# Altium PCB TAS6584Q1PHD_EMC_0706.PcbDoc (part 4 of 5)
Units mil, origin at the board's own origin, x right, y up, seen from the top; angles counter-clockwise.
Board outline 7086.61 x 5118.11 mil, 6 copper layers (Top Layer, GND02, SIG03, SIG04, GND05, Bottom Layer), stack 60.484 mil thick; 461 components, 247 nets, 1337 pads, 1658 vias.
Unrouted connection lines stored in the file: 67.
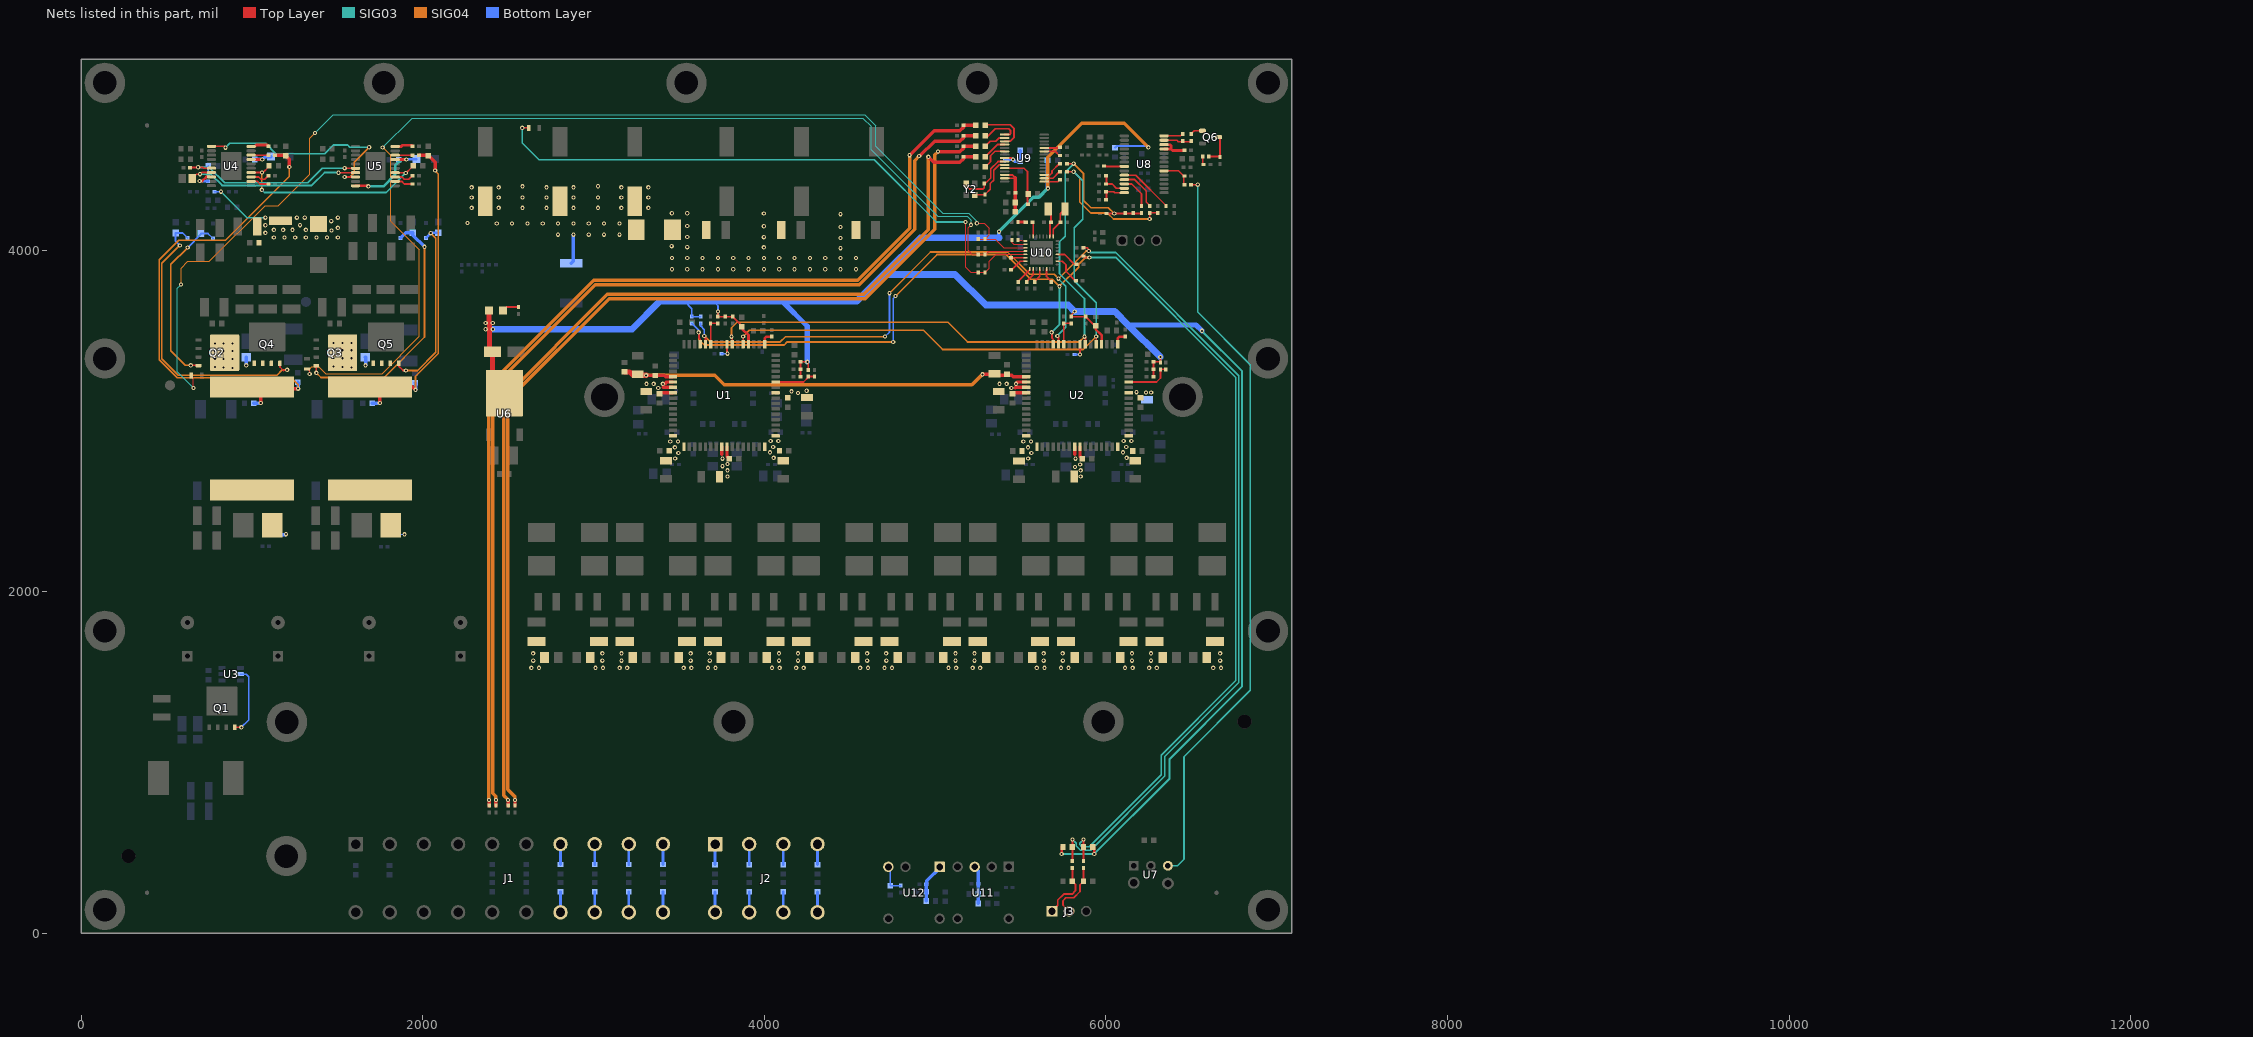
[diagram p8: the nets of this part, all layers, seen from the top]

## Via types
v1: diameter 25, hole 12, Top Layer to Bottom Layer, 1387 vias
v2: diameter 25, hole 12, Top Layer to Bottom Layer, tented both sides, 242 vias
v3: diameter 19.68, hole 7.87, Top Layer to Bottom Layer, 29 vias

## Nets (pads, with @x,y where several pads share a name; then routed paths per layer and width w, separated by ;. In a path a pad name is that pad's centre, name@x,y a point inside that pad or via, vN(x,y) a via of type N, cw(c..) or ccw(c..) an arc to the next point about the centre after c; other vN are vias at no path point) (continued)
NetC187_1: C187.1 J3.2 R123.2 | length 345.1
  Top Layer w10: J3.2@5784,130 5748.38,165.62 5748.38,191.33 5764.85,207.8 5811,207.8 5848.1,244.9 5848.1,284.66 C187.1@5868.5,305.05 R123.2@5868.5,383.6
NetC189_1: C189.1 J3.1 R122.2 | length 346.3
  Top Layer w10: J3.1@5684,130 5717.8,163.8 5717.8,195.2 5752.59,230 5801.55,230 5821,249.46 5821,288.24 C189.1@5803.5,305.75 R122.2@5803.5,383.6
NetC195_1: C195.1 R128.1 R132.2 | length 6203.1
  Top Layer w20: R128.1@2387.8,747.48 v1(2387.8,781.16) ; v1(4849.88,4557.1) 4993.71,4700.93 5144.93,4700.93 5166.04,4722.04 R132.2@5166.04,4731.47 C195.1@5237.68,4731.47
  SIG04 w20: v1(2387.8,781.16) 2385.04,783.92 2385.04,2960.18 2385.04,3020.01 2385.04,3209.6 2999.76,3824.32 3189.36,3824.32 4546.06,3824.32 4849.88,4128.14 v1(4849.88,4557.1)
NetC195_2: C195.2 U9.3 | length 295.9
  Top Layer w11: C195.2@5292.79,4731.47 5296.33,4735 5440.43,4735 5461,4714.43 5461,4660 5439.43,4638.43 U9.3@5406.61,4638.43
NetC196_1: C196.1 R129.1 R133.2 | length 6028.4
  Top Layer w20: R129.1@2498.8,747.48 v1(2498.8,781.16) ; v1(4960,4547.07) 4990.53,4516.53 5144.93,4516.53 5166.04,4537.64 R133.2@5166.04,4547.07 C196.1@5237.68,4547.07
  SIG04 w20: v1(2498.8,781.16) 2472.51,807.45 2472.51,2976.94 2472.51,3133.76 3080.57,3741.82 3237.39,3741.82 4581.18,3741.82 4960,4120.64 4960,4501.69 v1(4960,4547.07)
NetC196_2: C196.2 U9.4 | length 143.5
  Top Layer w11: C196.2@5292.79,4547.07 5334.47,4588.74 5364.47,4618.74 U9.4@5406.61,4618.74
NetC197_1: C197.1 R130.1 R134.2 | length 6137.7
  Top Layer w20: R130.1@2427.8,747.48 v1(2427.8,781.16) ; v1(4906.25,4552.44) 4910.26,4552.44 4997.28,4639.47 5144.93,4639.47 5166.04,4660.58 R134.2@5166.04,4670 C197.1@5237.68,4670
  SIG04 w20: v1(2427.8,781.16) 2427.8,803.54 2410.04,821.29 2410.04,3199.25 3010.12,3799.32 4556.41,3799.32 4879.38,4122.29 4879.38,4525.56 v1(4906.25,4552.44)
NetC197_2: C197.2 U9.1 | length 226.1
  Top Layer w11: C197.2@5292.79,4670 5310.85,4670 5352.85,4712 5431,4712 5442,4701 5442,4684 5435.8,4677.8 U9.1@5406.61,4677.8
NetC198_1: C198.1 R131.1 R135.2 | length 6009.3
  Top Layer w20: R131.1@2539.21,747.48 v1(2539.21,781.16) ; v1(5017,4578) 5144.93,4578 5166.04,4599.11 R135.2@5166.04,4608.53 C198.1@5237.68,4608.53
  SIG04 w20: v1(2539.21,781.16) 2539.21,800.59 2497.51,842.3 2497.51,3123.41 3090.92,3716.82 4591.54,3716.82 4997.87,4123.15 4997.87,4558.87 v1(5017,4578)
NetC198_2: C198.2 U9.2 | length 134.4
  Top Layer w11: C198.2@5292.79,4608.53 5322.79,4638.53 5355.53,4638.53 5375.11,4658.11 U9.2@5406.61,4658.11
NetC199_2: C199.2 U9.9 Y2.1 | length 356.3
  Top Layer w10: Y2.1@5182.95,4389.68 5182.95,4377.05 5201.57,4358.43 5278.43,4358.43 5286.78,4366.78 C199.2@5286.78,4390.28 5291.98,4390.28 5325,4423.3 5325,4477 5368.31,4520.31 U9.9@5406.61,4520.31
NetC200_2: C200.2 U9.10 Y2.3 | length 302.5
  Top Layer w10: Y2.3@5232.16,4324.72 5285.9,4324.72 C200.2@5291.78,4330.59 ; C200.2@5291.78,4326.65 5323.08,4357.95 5323.08,4391.24 5343,4411.17 5343,4469.28 5374.35,4500.63 U9.10@5406.61,4500.63
NetC201_2: C201.2 C202.1 U9.11 | length 332.6
  Top Layer w10: U9.11@5406.61,4480.94 5520.06,4480.94 5540,4461 5540,4330 C201.2@5540,4270
NetC203_1: C203.1 U9.6 | length 170.1
  Top Layer w10: C203.1@5293.55,4489.01 5323.72,4519.18 5323.72,4552.69 5350.41,4579.37 U9.6@5406.61,4579.37
NetC204_1: C204.1 C205.2 R138.1 U9.13 U9.14 | length 330.6
  Top Layer w11: U9.14@5406.61,4421.89 5466.67,4421.89 5468.89,4424.11 5451.43,4441.57 U9.13@5406.61,4441.57
  Top Layer w20: R138.1@5468.89,4226.25 C204.1@5468.89,4280 C205.2@5468.89,4337.09 5468.89,4424.11
NetC206_1: C206.1 C207.2 R142.1 U9.8 | length 215.2
  Top Layer w10: U9.8@5406.61,4540 5447,4540 v1(5455,4532)
  Bottom Layer w20: C207.2@5406.61,4520.31 5418.3,4532 v1(5455,4532) 5465.21,4521.79 C206.1@5498.58,4521.79 R142.1@5498.58,4584.29
NetC210_1: C210.1 C212.2 L18.2 U11.3 | length 221.4
  Bottom Layer w20: U11.3@5231.16,387.45 5252.73,365.88 L18.2@5252.73,175
NetC211_1: C211.1 C213.2 L19.2 U12.1 | length 232.9
  Bottom Layer w20: L19.2@4946.65,190 4947.56,190.92 C211.1@4947.56,244.19 C213.2@4947.56,287.19 4950.32,289.95 4950.32,307.1 U12.1@5031.11,387.89
NetC216_2: C216.2 U10.26 Y3.2 | length 170.9
  Top Layer w10: Y3.2@5661.42,4242.13 5677.55,4225.99 C216.2@5677.55,4165 5671.92,4159.37 U10.26@5671.92,4080.24
NetC217_2: C217.2 U10.25 Y3.1 | length 190.2
  Top Layer w10: U10.25@5691.61,4080.24 5691.61,4123.89 C217.2@5732.72,4165 5732.72,4215 Y3.1@5759.85,4242.13
NetD5_2: D5.2 R86.2 | length 99
  Top Layer w10: D5.2@2469.37,3647.93 2489.06,3667.61 R86.2@2560.18,3667.61
NetD6_2: D6.2 Q2.4 R95.2 | length 1040.1
  Top Layer w10: v1(640.71,3326.19) 684.25,3326.19 Q2.4@685.65,3324.8
  SIG04 w10: v1(622.29,4015.75) 523.89,3917.35 523.89,3411.58 609.28,3326.19 v1(640.71,3326.19)
  Bottom Layer w10: v1(622.29,4015.75) 700.1,4093.55 R95.2@700.1,4098.34 741.13,4098.34 D6.2@770.54,4068.93
NetD7_2: D7.2 Q3.4 R96.2 | length 1507.9
  Top Layer w10: v1(1376,3282.15) Q3.4@1376,3324.8
  SIG04 w10: v1(1376,3282.15) 1402.92,3255.24 1773.03,3255.24 2009.62,3491.83 v1(2009.62,4020.39)
  Bottom Layer w20: D7.2@1869.81,4073.31 1899.14,4102.64 R96.2@1940.92,4102.64 1940.92,4089.08 v1(2009.62,4020.39)
NetD8_2: D8.2 Q4.4 R97.2 | length 1733.1
  Top Layer w10: Q4.4@1162.83,3337.98 1162.83,3316.76 1183.53,3296.07 1184.7,3297.24 1202.08,3297.24 v1(1204.95,3300.11)
  SIG04 w10: v1(576.81,4028.63) 471.3,3923.12 471.3,3364.63 566.89,3269.04 1145.43,3269.04 1176.49,3300.11 v1(1204.95,3300.11)
  Bottom Layer w10: v1(576.81,4028.63) 551.87,4053.57 R97.2@551.87,4101.42 592.96,4101.42 D8.2@622.29,4072.09
NetD9_2: D9.2 Q5.4 R98.2 | length 1080.7
  Top Layer w10: Q5.4@1859.32,3337.98 1859.32,3320.73 1883.99,3296.07 v1(1900.31,3296.07)
  SIG04 w10: v1(1900.31,3296.07) 1969.36,3296.07 2075.28,3401.98 2075.28,4070.58 v1(2045.88,4099.98)
  Bottom Layer w15: D9.2@2018.5,4073.31 2047.83,4102.64 R98.2@2089.62,4102.64
NetD12_1: D12.1 Q6.3 R127.2 | length 181.5
  Top Layer w10: D12.1@6602.93,4549.69 6668,4549.69 6668,4654.09 Q6.3@6659.49,4662.6
NetD12_2: D12.2 R124.1 | length 47.2
  Top Layer w10: R124.1@6567.5,4502.45 D12.2@6567.5,4549.69
NetD13_1: D13.1 R143.2 | length 41.7
  Top Layer w16: D13.1@5484.58,4165 R143.2@5526.25,4165
NetL12_1: L12.1 R89.2 R91.1 | length 64.9
  Top Layer w20: R89.2@1105.98,2379.13 R89.2@1116.86,2390 R89.2@1125.98,2380.88
  Bottom Layer w20: R91.1@1163.06,2334.12 1194.83,2334.12 v1(1198.28,2337.57)
NetL13_1: L13.1 R90.2 R92.1 | length 35.7
  Bottom Layer w6: R92.1@1857.44,2337.36 1891.8,2337.36 v1(1892.76,2336.4)
NetQ1_4: Q1.4 U3.5 | length 407.5
  Top Layer w10: Q1.4@898.3,1206.42 v1(936.93,1206.42)
  Bottom Layer w10: U3.5@931.57,1517.81 965,1517.81 980,1502.81 980,1249.49 v1(936.93,1206.42)
NetQ6_1: Q6.1 R119.1 | length 71.5
  Top Layer w10: R119.1@6500.28,4683.62 6516.65,4700 Q6.1@6565,4700
NetR8_1: R8.1 R9.1 U1.11 | length 166
  Top Layer w10: U1.11@3686.26,3450.2 3686.26,3570.14 R9.1@3684.29,3572.11 R8.1@3727.6,3572.11
NetR10_1: R10.1 R13.2 U1.59 | length 243.6
  Top Layer w10: U1.59@4065.2,3228.74 4228.81,3228.74 4256.45,3256.39 R10.1@4256.45,3260.75 R13.2@4292.95,3260.75
NetR15_1: R15.1 U1.1 | length 79.4
  Top Layer w15: U1.1@4001.22,3450.2 4001.22,3483.79 4011.92,3494.49 R15.1@4042.64,3494.49
NetR37_1: R37.1 R38.1 U2.11 | length 166
  Top Layer w10: U2.11@5753.62,3450.2 5753.62,3570.14 5751.65,3572.11 R37.1@5794.95,3572.11
NetR39_1: R39.1 R42.2 U2.59 | length 279
  Top Layer w10: U2.59@6132.55,3228.74 6296.16,3228.74 6319.53,3252.1 R39.1@6319.53,3302.99 R42.2@6351.02,3302.99
NetR44_1: R44.1 U2.1 | length 79.4
  Top Layer w15: U2.1@6068.58,3450.2 6068.58,3483.79 6079.28,3494.49 R44.1@6109.99,3494.49
NetR67_2: R67.2 U4.13 | length 115
  Top Layer w10: U4.13@994.17,4429.4 1039,4429.4 1051.99,4416.41 1060.19,4416.41 1074.15,4416.41 R67.2@1095.12,4437.38
NetR73_2: R73.2 U4.12 | length 108.2
  Top Layer w10: U4.12@994.17,4403.81 1030.56,4403.81 1046.15,4388.22 1069.43,4388.22 R73.2@1095.86,4388.22
NetR74_2: R74.2 U4.8 | length 129.1
  Top Layer w15: v1(692.82,4405.5) 707.69,4405.5 731.59,4429.4 U4.8@761.89,4429.4
  Bottom Layer w15: v1(692.82,4405.5) 694.51,4403.81 R74.2@742.2,4403.81
NetR76_2: R76.2 U4.20 | length 109.5
  Top Layer w16: U4.20@994.17,4608.54 1015.86,4608.54 1023.84,4616.52 1089.05,4616.52 R76.2@1097.03,4608.54
NetR77_2: R77.2 U4.18 | length 101.7
  Top Layer w10: U4.18@994.17,4557.36 994.37,4557.16 R77.2@1095.78,4557.16
NetR80_2: R80.2 U5.13 | length 115.1
  Top Layer w10: U5.13@1837.8,4429.01 1879.18,4429.01 1891.78,4416.41 1918.05,4416.41 R80.2@1939.02,4437.38
NetR82_2: R82.2 U5.12 | length 108.3
  Top Layer w10: U5.12@1837.8,4403.42 1876.2,4403.42 1891.4,4388.22 R82.2@1939.84,4388.22
NetR83_2: R83.2 U5.20 | length 108.5
  Top Layer w16: U5.20@1837.8,4608.15 1874.73,4608.15 1881.52,4614.93 1933.87,4614.93 R83.2@1940.65,4608.15
NetR84_2: R84.2 U5.18 | length 97.1
  Top Layer w10: U5.18@1837.8,4556.96 1934.64,4556.96 R84.2@1934.82,4556.79
NetR106_1: R106.1 U7.3 | length 4383.7
  Top Layer w10: R106.1@6502.24,4384.02 v1(6537.59,4384.02)
  SIG03 w10: U7.3@6362.9,395.86 6418.9,395.86 6456.85,433.81 6456.85,1034.72 6845.47,1423.34 6845.47,3330.53 6537.59,3638.41 v1(6537.59,4384.02)
NetR108_1: R108.1 R112.2 U8.13 | length 162.6
  Top Layer w10: R108.1@6003.62,4436.19 6003.62,4388.19 6035.81,4388.19 6061.17,4362.83 U8.13@6107.72,4362.83
NetR109_1: R109.1 R113.2 U8.14 | length 154.5
  Top Layer w10: R109.1@6003.62,4295 6003.62,4343 6045,4343 6050.76,4337.24 U8.14@6107.72,4337.24
NetR110_2: R110.2 U8.8 | length 120.4
  Top Layer w10: R110.2@5988.69,4494 6000.5,4494 6003.71,4490.79 U8.8@6107.72,4490.79
NetR111_1: R111.1 U8.25 U8.26 | length 182
  Top Layer w16: U8.25@6340,4593.15 6382,4593.15 ; U8.26@6340,4618.74 6375.29,4618.74 6382,4612.03 6382,4593.15 ; R111.1@6455,4585 6390.15,4585 6382,4593.15
NetR114_1: R114.1 U8.28 | length 115.7
  Top Layer w10: U8.28@6340,4669.92 6436.3,4669.92 R114.1@6450,4683.62
NetR114_2: R114.2 R119.2 U8.27 | length 163.6
  Top Layer w10: U8.27@6340,4644.33 6415.67,4644.33 6423.62,4636.38 6450,4636.38 R119.2@6500.28,4636.38
NetR115_1: R115.1 U8.11 | length 249
  Top Layer w10: U8.11@6107.72,4414.02 6168.98,4414.02 6236,4347 6236,4282.63 R115.1@6256.23,4262.4
NetR116_1: R116.1 U8.10 | length 317.6
  Top Layer w10: U8.10@6107.72,4439.61 6174.74,4439.61 R116.1@6351.94,4262.4
NetR117_1: R117.1 U8.12 | length 192.6
  Top Layer w10: U8.12@6107.72,4388.43 6150.22,4388.43 6208.37,4330.28 R117.1@6208.37,4262.4
NetR136_2: R136.2 U9.25 | length 98.5
  Top Layer w10: U9.25@5638.9,4579.37 5703.27,4579.37 R136.2@5727.4,4555.24
NetR137_2: R137.2 U9.26 | length 90.1
  Top Layer w10: U9.26@5638.9,4599.06 5723.5,4599.06 R137.2@5727.4,4602.95
NetR139_2: R139.2 U9.18 | length 122.6
  Top Layer w10: U9.18@5638.9,4441.57 5673.02,4441.57 5684,4452.56 5684,4464.13 R139.2@5727.4,4507.53
NetR140_2: R140.2 U9.16 | length 92.6
  Top Layer w10: U9.16@5638.9,4402.2 5717.5,4402.2 R140.2@5727.4,4412.1
NetR141_2: R141.2 U9.17 | length 104.2
  Top Layer w10: U9.17@5638.9,4421.89 5689.48,4421.89 R141.2@5727.4,4459.81
NetR143_1: R143.1 U10.31 | length 84.8
  Top Layer w10: U10.31@5573.5,4080.24 R143.1@5573.5,4165
NetR146_1: R146.1 U10.7 | length 100.6
  Top Layer w10: R146.1@5448.3,3886.54 5498.3,3936.54 U10.7@5528.22,3936.54
NetR147_1: R147.1 U10.6 | length 79.9
  Top Layer w10: R147.1@5448.3,3956.22 U10.6@5528.22,3956.22
NetR148_1: R148.1 U10.12 | length 84.7
  Top Layer w10: R148.1@5583.77,3818.62 5612.87,3847.72 U10.12@5612.87,3891.26
NetR149_1: R149.1 U10.14 | length 84.4
  Top Layer w10: U10.14@5652.24,3891.26 5652.24,3846.92 R149.1@5680.54,3818.62
NetR150_1: R150.1 U10.18 | length 172.3
  Top Layer w10: U10.18@5717.2,3936.54 5744.46,3936.54 5766,3915 5766,3876.41 R150.1@5819.76,3822.65
NetR151_1: R151.1 U10.20 | length 126.4
  Top Layer w10: U10.20@5717.2,3975.91 5757.09,3975.91 5814.56,3918.44 R151.1@5819.76,3918.44
NetR152_1: R152.1 U10.1 | length 45.9
  Top Layer w6: R152.1@5484.53,4059.94 5506,4059.94 5511.3,4054.65 U10.1@5528.22,4054.65
NetR153_1: R153.1 U10.2 | length 96.9
  Top Layer w6: R153.1@5449.53,4059.94 5449.53,4046.47 5461.04,4034.96 U10.2@5528.22,4034.96
NetR154_1: R154.1 R156.2 U12.4 | length 171.8
  Bottom Layer w10: U12.4@4731.11,387.89 4736.22,382.78 R156.2@4736.22,279.65 R154.1@4797.63,279.65
NetR158_2: R158.2 U10.9 | length 100.3
  Top Layer w10: R158.2@5487,3818.62 5553.81,3885.43 U10.9@5553.81,3891.26
NetR159_2: R159.2 U10.10 | length 88.4
  Top Layer w10: R159.2@5535.38,3818.62 5573.5,3856.74 U10.10@5573.5,3891.26
NTC1: C228.2 R52.1 RT1.2 U10.3 | length 6778.9
  Top Layer w6: RT1.2@643.84,3267.34 656.25,3254.93 v1(656.25,3194.2) ; v1(5243.97,4158.32) 5288.61,4158.32 5316.44,4130.5 5316.44,4090.52 C228.2@5291.98,4066.06 ; R52.1@5252.91,4066.06 C228.2@5291.98,4066.06 ; U10.3@5528.22,4015.28 5401.11,4015.28 5350.32,4066.06 C228.2@5291.98,4066.06
  SIG04 w6: v1(583.79,3799.38) 583.79,3895.89 622.29,3934.39 748.96,3934.39 1075.72,4261.16 1152.82,4261.16 1337.01,4445.35 1337.01,4655.81 v1(1368.33,4687.14)
  SIG03 w6: v1(583.79,3799.38) 560.68,3776.27 560.68,3289.77 v1(656.25,3194.2) ; v1(1368.33,4687.14) 1475.19,4794 4586.22,4794 4652.22,4728 4652.22,4608.8 5043.22,4217.8 5195.21,4217.8 5243.97,4169.04 v1(5243.97,4158.32)
NTC2: C229.2 R65.1 RT2.2 U10.4 | length 6395.3
  Top Layer w6: RT2.2@1322.47,3305.01 1337.26,3290.22 v1(1337.26,3274.97) ; v1(5209.88,4148.8) 5193.25,4132.16 5193.25,3999.73 5217.97,3975.02 R65.1@5252.91,3975.02 C229.2@5291.98,3975.02 5312.55,3995.59 U10.4@5528.22,3995.59
  SIG04 w6: v1(1337.26,3274.97) 1337.26,3303.99 1350.02,3316.76 1390.93,3316.76 1430.03,3277.66 1760.66,3277.66 1980,3497 1980,4002.01 1810.88,4171.12 1810.88,4556.06 v1(1764.77,4602.17)
  SIG03 w6: v1(1764.77,4602.17) 1936.61,4774 4577,4774 4626,4725 4626,4588.2 5015.74,4198.46 5187,4198.46 5209.88,4175.58 v1(5209.88,4148.8)
NTC3: C230.2 R66.1 RT3.2 U10.5 | length 3603.1
  Top Layer w6: v1@5177.96,4159.37 5177.96,3900.43 5207.07,3871.31 R66.1@5252.91,3871.31 C230.2@5291.98,3871.31 5316.44,3895.77 5316.44,3935.36 5356.98,3975.91 5388.88,3975.91 5389.04,3976.06 5420.95,3976.06 5421.1,3975.91 5428.25,3975.91 5428.41,3976.06 5460.32,3976.06 5460.47,3975.91 U10.5@5528.22,3975.91
  Top Layer w10: v1(2581.85,4717) RT3.2@2620.55,4717
  SIG03 w10: v1(2581.85,4717) 2581.85,4628.14 2679.99,4530 4643.59,4530 5007.59,4166 v1(5177.96,4166)
PVDD: C2.1 C3.1 C4.1 C5.1 C6.1 C7.1 C8.1 C9.1 C15.1 C17.1 C60.1 C61.1 C62.1 C63.1 C64.1 C65.1 C66.1 C67.1 C73.1 C75.1 J5.2 R103.2 R104.2 R105.2 U1.22 U1.23 U1.24 U1.32 U1.33 U1.40 U1.41 U1.48 U1.49 U1.57 U2.22 U2.23 U2.24 U2.32 U2.33 U2.40 U2.41 U2.48 U2.49 U2.57 | length 634.8
  Top Layer w20: C6.1@3385.71,3160.67 3390.78,3165.75 U1.24@3464.8,3165.75 ; 3407.97,3197.24 U1.23@3464.8,3197.24 ; 3420,3220 3428.74,3228.74 U1.22@3464.8,3228.74 ; 3749.25,2805.42 U1.40@3749.25,2849.8 ; U1.41@3780.75,2849.8 3780.75,2792.95 C7.1@3793.7,2780 ; C65.1@5453.06,3160.67 5458.14,3165.75 U2.24@5532.16,3165.75 ; 5469.07,3194.69 5471.63,3197.24 U2.23@5532.16,3197.24 ; v2(5472.61,3218.28) 5483.08,3228.74 U2.22@5532.16,3228.74 ; 5816.61,2805.42 U2.40@5816.61,2849.8 ; U2.41@5848.1,2849.8 5848.1,2792.95 C64.1@5861.05,2780
  other v1: 4054.22,2784.86 6121.57,2784.86 4032.06,2816.79 6099.42,2816.79 4051.32,2848.77 6118.68,2848.77 4036.34,2882.65 6103.69,2882.65 4081.3,2883.3 6148.65,2883.3 4197.06,3164.08 6234.4,3166.73 6264.42,3166.73 6179.09,3169.3 4157.88,3173.83 4247.18,3177.61 3458.32,3889.08 3548.1,3889.08 3637.87,3889.08 3727.65,3889.08 3817.43,3889.08 3907.2,3889.08 3996.98,3889.08 4086.75,3889.08 4176.53,3889.08 4266.31,3889.08 4356.08,3889.08 4445.86,3889.08 4535.64,3889.08 3458.32,3955 3548.1,3955 3637.87,3955 3727.65,3955 3817.43,3955 3907.2,3955 3996.98,3955 4086.75,3955 4176.53,3955 4266.31,3955 4356.08,3955 4445.86,3955 4535.64,3955 4445.8,4012.64 3996.2,4017.11 3548.1,4018.2 3457.08,4024.02 4445.8,4072.25 3996.2,4076.73 3548.1,4077.82 4445.8,4136.43 3996.2,4140.91 3548.1,4142 4445.8,4211.43 3996.2,4215.91 3458,4217 3548.1,4217
  other v2: 3784.43,2674.8 5851.78,2674.8 3784.43,2711.52 5851.78,2711.52 5818.18,2730.55 3754.82,2735.55 5848.78,2745.24 3784.43,2748.24 3754.82,2779.48 5822.18,2779.48 3477.25,2780.79 5544.61,2780.79 3495.83,2812.92 5563.18,2812.92 3475.49,2846.24 5542.84,2846.24 3448.63,2879.95 5515.98,2879.95 3493.32,2880.26 5560.67,2880.26 3378.29,3194.1 5445.65,3194.1 3309.63,3218 3351.11,3218 5376.99,3218 5418.46,3218 3405.26,3218.28
RES: C141.1 C219.1 U4.14 U5.14 | length 1232.8
  Top Layer w10: U4.14@994.17,4454.99 1054.19,4454.99 1056.37,4457.18 1065.92,4457.18 C141.1@1096.22,4487.48 ; U5.14@1837.8,4454.6 1896.23,4454.6 1899.75,4451.08 1936.14,4487.48 C219.1@1939.84,4487.48
  SIG04 w10: v1(1056.61,4353.99) 1056.61,4454.36 v1(1057.3,4455.05)
  SIG03 w10: v1(1056.61,4353.99) 1072.6,4338 1784.67,4338 v1(1899.75,4453.08)
RXIN: C178.1 R106.2 U8.20 | length 178.6
  Top Layer w10: U8.20@6340,4465.2 6425,4465.2 6455,4435.2 R106.2@6455,4384.02
SCL: R1.1 R120.1 R123.1 R144.2 U1.13 U2.13 | length 7890.3
  Top Layer w10: v1(3614.73,3519.37) 3616.89,3517.2 3616.89,3485.82 3623.27,3479.44 U1.13@3623.27,3450.2 ; v1(5682.08,3519.37) 5684.25,3517.2 5684.25,3485.82 5690.62,3479.44 U2.13@5690.62,3450.2 ; R144.2@5868.07,3966.33 5876.01,3958.38 v1(5902.81,3958.38) ; R123.1@5868.5,422.97 v1(5868.5,550)
  SIG04 w10: v1(3614.73,3519.37) 3614.73,3477.86 3647.59,3445 4116.11,3445 4134.68,3463.57 4753.43,3463.57 v1(4754,3463) ; v1(4768,3732) 5010.86,3974.86 5415.97,3974.86 5559.78,3831.05 5685.35,3831.05 v1(5727.4,3789) 5840,3901.6 5840,3917.25 5881.14,3958.38 v1(5902.81,3958.38)
  SIG03 w10: v1(5682.08,3519.37) 5727.4,3564.68 v1(5727.4,3789) ; v1(5868.5,550) 5846,527.5 5846,520 5859,507 5901.61,507 6324,929.39 6324,1043.77 6760.78,1480.55 6760.78,3254.94 6057.33,3958.38 v1(5902.81,3958.38)
  Bottom Layer w10: R1.1@3575.2,3572.11 3614.73,3532.57 v1(3614.73,3519.37) ; v1(4754,3463) 4754,3718 v1(4768,3732)
SCLK: C185.1 R115.2 R141.1 U1.5 U2.5 | length 4073.4
  Top Layer w10: U1.5@3875.24,3450.2 v1(3875.24,3495.21) ; R141.1@5774.64,4459.81 v1(5811,4459.81) ; U2.5@5942.59,3450.2 v1(5942.59,3495.21) ; v1(6256.23,4182.94) R115.2@6256.22,4219.09 C185.1@6304.08,4219.09
  SIG04 w10: v1(3875.24,3495.21) 3911.03,3531 4931.25,3531 5043.22,3419.03 5866.42,3419.03 v1(5942.59,3495.21) ; v1(5811,4459.81) 5847,4423.81 5847,4283 5912.2,4217.8 6008.98,4217.8 6043.84,4182.94 v1(6256.23,4182.94)
  SIG03 w10: v1(5811,4459.81) 5864,4406.81 5864,4181 5814,4131 5814,3821 5942.59,3692.41 v1(5942.59,3495.21)
SDA: R3.1 R121.1 R122.1 R145.2 U1.12 U2.12 | length 7940.5
  Top Layer w10: v1(3647.59,3498.56) 3654.76,3491.39 U1.12@3654.76,3450.2 ; v1(5714.95,3498.56) 5722.12,3491.39 U2.12@5722.12,3450.2 ; R122.1@5803.5,422.97 v1(5803.5,550) ; R145.2@5868.07,4014.22 5889.5,4014.22 5899.27,4004.45 v1(5899.27,3995.3)
  SIG04 w10: v1(3647.59,3498.56) 3682.58,3463.57 4092.94,3463.57 4123.56,3494.19 4705.2,3494.19 v1(4706.21,3495.21) ; v1(4732,3749) 4972.86,3989.86 5423.7,3989.86 5554.64,3858.91 5697.21,3858.91 v1(5722.12,3834) 5814,3925.88 5883.42,3995.3 v1(5899.27,3995.3)
  SIG03 w10: v1(5714.95,3498.56) 5764.84,3548.45 5764.84,3789 5722.12,3831.72 v1(5722.12,3834) ; v1(5803.5,550) 5826,527.5 5826,511.72 5850.72,487 5909.9,487 6344,921.1 6344,1035.49 6777.92,1469.41 6777.92,3266.08 6057,3987 5907.57,3987 v1(5899.27,3995.3)
  Bottom Layer w10: R3.1@3626.19,3572.11 3626.19,3557.11 3647.59,3535.71 v1(3647.59,3498.56) ; v1(4706.21,3495.21) 4732,3521 v1(4732,3749)
SDIN: C188.1 R117.2 R125.2 R126.2 R139.1 U1.7 U2.7 | length 4085
  Top Layer w10: v1(3807.06,3494.19) 3812.24,3489.01 U1.7@3812.24,3450.2 ; R139.1@5774.64,4507.53 v1(5811,4507.53) ; v1(5874.42,3494.19) 5879.6,3489.01 U2.7@5879.6,3450.2 ; R125.2@6003.62,4215.16 R117.2@6208.37,4215.16
  SIG04 w10: v1(3807.06,3494.19) 3807.06,3546 3839.49,3578.42 5074.58,3578.42 5189.43,3463.57 5843.8,3463.57 v1(5874.42,3494.19) ; v1(5811,4507.53) 5868,4450.53 5868,4294 5912.5,4249.5 6014.3,4249.5 v1(6048.64,4215.16)
  SIG03 w10: v1(5811,4507.53) 5761,4457.53 5761,4083 5728,4050 5728,3863.66 5874.42,3717.24 v1(5874.42,3494.19)
SDOUT1: R40.1 U2.8 | length 96.6
  Top Layer w10: v1(5848.1,3390.15) U2.8@5848.1,3450.2
  Bottom Layer w10: R40.1@5814.57,3387.99 R40.1@5816.74,3390.15 ; R40.1@5814.57,3390.15 R40.1@5816.74,3390.15 ; v1(5848.1,3390.15) R40.1@5816.74,3390.15
SDOUT2: R11.1 U1.8 | length 92.1
  Top Layer w10: U1.8@3780.75,3450.2 3780.75,3397.15 v1(3783.1,3394.8)
  Bottom Layer w10: R11.1@3747.33,3394.8 v1(3783.1,3394.8)
SPK_OUT1+: C49.1 C57.1 J1.14 R30.2 | length 120
  Bottom Layer w16: J1.14@2806,123 C57.1@2806,243
  other v1: 3010.34,1554.79 3055.25,1554.75 3051.04,1597.09 3051.04,1639.98
SPK_OUT1-: C50.1 C58.1 J1.13 R31.2 | length 120
  Bottom Layer w16: C58.1@2806,403 J1.13@2806,523
  other v1: 2635.24,1554.79 2679.27,1554.79 2646.23,1597.09 2645.52,1639.98
SPK_OUT2+: C47.1 C55.1 J1.16 R28.2 | length 120
  Bottom Layer w16: J1.16@3006,123 C55.1@3006,243
  other v1: 3527.2,1554.79 3572.11,1554.75 3567.9,1597.09 3567.9,1639.98
SPK_OUT2-: C48.1 C56.1 J1.15 R29.2 | length 120
  Bottom Layer w16: C56.1@3006,403 J1.15@3006,523
  other v1: 3152.1,1554.79 3196.13,1554.79 3163.09,1597.09 3162.38,1639.98
SPK_OUT3+: C45.1 C53.1 J1.18 R26.2 | length 120
  Bottom Layer w16: J1.18@3206,123 C53.1@3206,243
  other v1: 4044.06,1554.79 4088.97,1554.75 4084.76,1597.09 4084.76,1639.98
SPK_OUT3-: C46.1 C54.1 J1.17 R27.2 | length 120
  Bottom Layer w16: C54.1@3206,403 J1.17@3206,523
  other v1: 3668.96,1554.79 3712.99,1554.79 3679.95,1597.09 3679.24,1639.98
SPK_OUT4+: C43.1 C51.1 J1.20 R24.2 | length 120
  Bottom Layer w16: J1.20@3406,123 C51.1@3406,243
  other v1: 4560.92,1554.79 4605.83,1554.75 4601.62,1597.09 4601.62,1639.98
SPK_OUT4-: C44.1 C52.1 J1.19 R25.2 | length 120
  Bottom Layer w16: C52.1@3406,403 J1.19@3406,523
  other v1: 4185.83,1554.79 4229.85,1554.79 4196.81,1597.09 4196.1,1639.98
SPK_OUT5+: C107.1 C115.1 J2.2 R59.2 | length 120
  Bottom Layer w16: J2.2@3711,122.65 C115.1@3711,242.65
  other v1: 5077.78,1554.79 5122.69,1554.75 5118.48,1597.09 5118.48,1639.98
SPK_OUT5-: C108.1 C116.1 J2.1 R60.2 | length 120
  Bottom Layer w16: C116.1@3711,402.65 J2.1@3711,522.65
  other v1: 4702.69,1554.79 4746.71,1554.79 4713.68,1597.09 4712.96,1639.98
SPK_OUT6+: C105.1 C113.1 J2.4 R57.2 | length 120
  Bottom Layer w16: J2.4@3911,122.65 C113.1@3911,242.65
  other v1: 5594.64,1554.79 5639.55,1554.75 5635.34,1597.09 5635.34,1639.98
SPK_OUT6-: C106.1 C114.1 J2.3 R58.2 | length 120
  Bottom Layer w16: C114.1@3911,402.65 J2.3@3911,522.65
  other v1: 5219.55,1554.79 5263.57,1554.79 5230.54,1597.09 5229.82,1639.98
SPK_OUT7+: C103.1 C111.1 J2.6 R55.2 | length 120
  Bottom Layer w16: J2.6@4111,122.65 C111.1@4111,242.65
  other v1: 6111.5,1554.79 6156.41,1554.75 6152.2,1597.09 6152.2,1639.98
SPK_OUT7-: C104.1 C112.1 J2.5 R56.2 | length 120
  Bottom Layer w16: C112.1@4111,402.65 J2.5@4111,522.65
  other v1: 5736.41,1554.79 5780.43,1554.79 5747.4,1597.09 5746.68,1639.98
SPK_OUT8+: C101.1 C109.1 J2.8 R53.2 | length 120
  Bottom Layer w16: J2.8@4311,122.65 C109.1@4311,242.65
  other v1: 6628.36,1554.79 6673.27,1554.75 6669.06,1597.09 6669.06,1639.98
SPK_OUT8-: C102.1 C110.1 J2.7 R54.2 | length 120
  Bottom Layer w16: C110.1@4311,402.65 J2.7@4311,522.65
  other v1: 6253.27,1554.79 6297.29,1554.79 6264.26,1597.09 6263.54,1639.98
SS: C128.1 U4.7 U5.7 | length 1112.9
  Top Layer w10: C128.1@663.71,4420.32 C128.1@648.75,4420.32 674.12,4445.69 v1(695.08,4445.69) ; v1@695.08,4445.27 704.81,4454.99 U4.7@761.89,4454.99 ; v1(1505.65,4453.99) 1506.27,4454.6 U5.7@1605.51,4454.6 U5.7@1604.9,4453.99
  SIG03 w10: v1(695.08,4445.69) 758.47,4445.69 824.14,4380.02 1348.98,4380.02 1424.01,4455.05 1504.59,4455.05 v1(1505.65,4453.99)
SW1: C132.2 C154.1 C156.1 D11.2 L12.2 Q2.5 Q2.6 Q2.7 Q2.8 Q2.9@839.19,3399.8 Q4.1 Q4.2 Q4.3 R77.1 | length 3145.5
  Top Layer w20: L12.2@998.21,3199.74 L12.2@1008.49,3189.46 ; v1(1050.58,3105.15) 1050.58,3147.37 L12.2@1008.49,3189.46 ; R77.1@1135.15,4557.16 1193.64,4557.16 1218.03,4532.77 v1(1218.03,4487.48) ; v1(1269.76,3189.46) L12.2@1008.49,3189.46
  SIG04 w10: v1(1218.03,4487.48) 1218.03,4432.36 844.36,4058.69 570.43,4058.69 456.3,3944.56 456.3,3358.42 560.68,3254.04 1228.96,3254.04 1269.76,3213.24 v1(1269.76,3189.46)
  Bottom Layer w20: D11.2@965.06,3374.53 965.48,3374.12 v1(965.48,3326.19) ; C154.1@1010.29,3104.94 1010.5,3105.15 v1(1050.58,3105.15) ; C156.1@1267.77,3227.04 1269.76,3225.04 v1(1269.76,3189.46)
  other v1: 885.34,3311.59 832.92,3314.4 781.57,3316.76 781.57,3365.01 832.92,3364.63 885.34,3364.63 781.57,3411.58 832.92,3411.58 885.34,3411.58 781.57,3455 832.92,3455 885.34,3455
SW2: C144.2 C155.1 C157.1 D10.2 L13.2 Q3.5 Q3.6 Q3.7 Q3.8 Q3.9@1529.55,3399.8 Q5.1 Q5.2 Q5.3 R84.1 | length 2031.3
  Top Layer w20: v1(1747.98,3105.39) 1747.98,3142.67 L13.2@1690.91,3199.74 1936.82,3199.74 v1@1953.98,3182.58 ; R84.1@1978.39,4556.77 2028.84,4556.77 C144.2@2032.19,4553.42 2034.7,4553.42 2071.85,4516.27 v1(2071.85,4467.4)
  SIG04 w10: v1(1956.98,3182.58) 1956.98,3262.47 2090.28,3395.77 2090.28,4446.93 2071.85,4465.35 v1(2071.85,4467.4)
  Bottom Layer w20: D10.2@1663.36,3374.53 1664.32,3373.57 v1(1664.32,3326.38) ; C155.1@1703.24,3104.94 1703.69,3105.39 v1(1747.98,3105.39) ; C157.1@1953.98,3224.24 1956.98,3221.24 v1(1956.98,3182.58)
  other v1: 1580.79,3314.67 1528.37,3317.47 1477.02,3319.83 1477.02,3368.09 1528.37,3367.71 1580.79,3367.71 1477.02,3414.66 1528.37,3414.66 1580.79,3414.66 1477.02,3458.07 1528.37,3458.07 1580.79,3458.07
SYNC: U4.1 U5.8 | length 1303.2
  Top Layer w10: U4.1@761.89,4608.54 836.15,4608.54 v1(843.97,4600.72) ; v1(1541.97,4429.01) U5.8@1605.51,4429.01
  SIG04 w10: v1(1541.97,4429.01) 1572.61,4429.01 1598.2,4454.6 1598.2,4516.36 v1(1685.18,4603.34)
  SIG03 w10: v1(843.97,4600.72) 869.23,4625.98 1079.58,4625.98 1139.37,4566.19 1424.61,4566.19 1474.94,4616.52 1559.26,4616.52 1572.44,4603.34 v1(1685.18,4603.34)
UVLO: C123.1 R69.1 R70.2 U4.6 U5.6 | length 1231.4
  Top Layer w10: R69.1@637.22,4484 638.48,4485.26 711.34,4485.26 716.02,4480.59 U4.6@761.89,4480.59 ; v1(1541.97,4480.59) 1542.36,4480.19 U5.6@1605.51,4480.19
  SIG03 w10: v1(684.16,4486.26) 685.18,4485.24 749.39,4485.24 839.61,4395.02 1325.38,4395.02 1410.95,4480.59 v1(1541.97,4480.59)
  Bottom Layer w10: v1(684.16,4486.26) 736.38,4486.26 C123.1@743.3,4493.19 R70.2@743.3,4445.69
V_boost: C167.1 C168.1 C169.2 C170.2 C171.2 J5.1 L14.2 R61.1 R101.2 R102.1 | length 533.9
  SIG03 w10: v1(817.82,4343.34) 970.34,4190.83 v1(1077.2,4190.83)
  Bottom Layer w10: R61.1@779.36,4343 817.48,4343 v1(817.82,4343.34)
  Bottom Layer w20: R102.1@2869,3924 2881.36,3936.36 v1(2881.36,4091.63)
  other v1: 1127.43,4075 1189.75,4075 1252.08,4075 1314.4,4075 1376.73,4075 1439.06,4075 1501.61,4075 2791.58,4091.63 2971.13,4091.63 3060.91,4091.63 3150.69,4091.63 1077.2,4102.21 1465,4115.25 1127.43,4119.84 1182.09,4119.84 1236.75,4119.84 1314.4,4119.84 1501.61,4131.42 1077.2,4146.52 1280.15,4147.4 2432.47,4157.43 2522.25,4157.43 2612.03,4157.43 2701.8,4157.43 2791.58,4157.43 2881.36,4157.43 2971.13,4157.43 3060.91,4157.43 3150.69,4157.43 2261.24,4160.34 1463.25,4170.4 1261.49,4190.83 1308.31,4190.83 1501.61,4190.83 2285.56,4248.94 2443.56,4248.94 2582.94,4248.94 2723.91,4248.94 2881.91,4248.94 3024.95,4248.94 3162.2,4248.94 3320.2,4248.94 2285.56,4308.94 2443.56,4308.94 2582.94,4308.94 2723.91,4308.94 2881.91,4308.94 3024.95,4308.94 3162.2,4308.94 3320.2,4308.94 2285.56,4368.94 2443.56,4368.94 2723.91,4368.94 2881.91,4368.94 3162.2,4368.94 3320.2,4368.94 2582.94,4374.32 3024.95,4375
VBAT: C16.1 C18.1 C74.1 C76.1 L1.1 U1.21 U2.21 | length 2578.6
  Top Layer w20: v2(3307.72,3268.11) 3308.83,3267 C16.1@3360,3267 3361.11,3268.11 3413.88,3268.11 3421.76,3260.24 U1.21@3464.8,3260.24 ; v1(5277.05,3273.95) 5343.35,3273.95 C76.1@5346.95,3277.55 5355.57,3268.94 5448.3,3268.94 5457,3260.24 U2.21@5532.16,3260.24
  Top Layer w30: L1.1@3180.41,3287.97 3181.2,3287.18 3210.97,3287.18 3230.04,3268.11 v2(3307.72,3268.11)
  SIG04 w20: v2(3307.72,3268.11) 3708.97,3268.11 3764.78,3212.3 5215.39,3212.3 v1(5277.05,3273.95)
VCC: C1.1 C59.1 C143.1 D5.1 L15.2 L16.2 L17.2 R1.2 R2.2 R3.2 R4.2 R5.2 R6.2 R7.2 R8.2 R10.2 R32.2 R33.2 R35.2 R36.2 R37.2 R39.2 R120.2 R121.2 U1.4 U2.4 U6.4 | length 13099.4
  Top Layer w8: R2.2@3814.21,3611.48 3867.8,3557.89 C1.1@3867.8,3552.45
  Top Layer w10: v1(3728.42,3642.03) 3728.42,3612.3 R8.2@3727.6,3611.48 R5.2@3770.9,3611.48 R2.2@3814.21,3611.48 ; R4.2@4210.68,3259.09 R6.2@4210.68,3303.09 R7.2@4210.68,3347.08 4211.04,3346.73 v1(4251,3346.73) 4256.45,3341.28 R10.2@4256.45,3300.12 ; v1(5816.69,3641.51) 5795.93,3620.75 R37.2@5795.93,3611.48 R32.2@5881.57,3611.48 5940.15,3552.89 C59.1@5940.15,3552.45 ; R33.2@6277.83,3259.09 R35.2@6277.83,3304.14 R36.2@6277.83,3346.73 6315.16,3346.73 R39.2@6319.53,3342.36 6319.53,3373.56 v1(6318.36,3374.73)
  Top Layer w15: C1.1@3872.8,3552.45 3872.8,3536.98 3906.73,3503.04 U1.4@3906.73,3450.2 ; C59.1@5940.15,3552.45 5940.15,3536.98 5974.09,3503.04 U2.4@5974.09,3450.2
  Top Layer w16: v1(5740.51,465.1) R121.2@5740.51,505.12 ; v1(5931.49,465.1) R120.2@5931.49,505.12
  Top Layer w30: D5.1@2386.69,3647.93 2386.69,3567.31 2389.12,3564.88 2389.12,3424.98 C143.1@2407.99,3406.1 2407.99,3232.41 U6.4@2476.89,3163.51
  SIG04 w20: v1(5660,4362.83) 5660,4544.47 5859.01,4743.47 6107.28,4743.47 v1(6247.8,4602.95)
  SIG03 w12: v1(5740.51,465.1) v1(5931.49,465.1) 6372,905.61 6372,1020.66 6797.46,1446.12 6797.46,3291.49 6562.14,3526.81 v1(6562.14,3528.5)
  SIG03 w20: v1(5373.18,4108.92) 5574.93,4310.67 5607.83,4310.67 v1(5660,4362.83)
  Bottom Layer w10: 3529,3703 3575.2,3656.8 R1.2@3575.2,3611.48 R3.2@3626.19,3611.48 ; 3699.12,3703 3728.42,3673.7 v1(3728.42,3642.03)
  Bottom Layer w12: L15.2@6053.36,4601.18 6062.13,4609.96 6240.8,4609.96 v1(6247.8,4602.95)
  Bottom Layer w20: L17.2@5373.18,4072.95 v1(5373.18,4108.92) ; L16.2@5657.15,4527.68 5657.15,4365.68 v1(5660,4362.83)
  Bottom Layer w30: 4108.82,3703 4108.82,3697.43 4251,3555.25 v1(4251,3346.73) ; 6130.2,3562.88 6527.76,3562.88 v1(6562.14,3528.5)
  Bottom Layer w40: v1(2409.47,3537.64) 3223.84,3537.64 3389.2,3703 3529,3703 3699.12,3703 4108.82,3703 4543,3703 4698.59,3858.59 ; L17.2@5373.18,4072.95 4912.95,4072.95 4698.59,3858.59 ; v1(6318.36,3374.73) 6130.2,3562.88 6051.58,3641.51 v1(5816.69,3641.51) 5779.15,3679.04 5296.12,3679.04 5116.58,3858.59 4698.59,3858.59
  other v1: 2367.82,3537.64 2367.58,3574.48 2408.99,3574.72
VCC1: C134.1 D3.2 U4.17 | length 163.1
  Top Layer w16: U4.17@994.17,4531.77 v1(1059.41,4531.77)
  Bottom Layer w20: C134.1@1018.74,4532.17 1060.13,4532.17 1076.74,4548.78 D3.2@1109.74,4548.78
VCC2: C145.1 D4.2 U5.10 U5.17 | length 566
  Top Layer w15: U5.10@1605.18,4378.16 U5.10@1605.51,4377.83 1677.27,4377.83 v1(1680.78,4374.32)
  Top Layer w16: U5.17@1837.8,4531.37 v1(1903.04,4531.37)
  SIG03 w15: v1(1680.78,4374.32) 1769.07,4374.32 1837.8,4443.04 1837.8,4495.39 1873.78,4531.37 v1(1903.04,4531.37)
  Bottom Layer w15: C145.1@1857.56,4530 1858.93,4531.37 v1(1903.04,4531.37) 1905.45,4533.78 D4.2@1961.62,4533.78
pads on no net: FID1.1 FID2.1 FID3.1 FID4.1 FID5.1 FID6.1 Q1.9@765.43,1310.36 Q1.9@765.43,1376.5 Q1.9@823.3,1310.36 Q1.9@823.3,1376.5 Q1.9@881.18,1310.36 Q1.9@881.18,1376.5 Q2.9@763.99,3306.39 Q2.9@763.99,3493.2 Q2.9@775.61,3347.44 Q2.9@775.61,3399.8 Q2.9@775.61,3452.16 Q2.9@820.88,3347.44 Q2.9@820.88,3399.8 Q2.9@820.88,3452.16 Q2.9@826.2,3399.8 Q2.9@866.16,3347.44 Q2.9@866.16,3399.8 Q2.9@866.16,3452.16 Q3.9@1454.35,3306.39 Q3.9@1454.35,3493.2 Q3.9@1465.96,3347.44 Q3.9@1465.96,3399.8 Q3.9@1465.96,3452.16 Q3.9@1511.24,3347.44 Q3.9@1511.24,3399.8 Q3.9@1511.24,3452.16 Q3.9@1516.55,3399.8 Q3.9@1556.52,3347.44 Q3.9@1556.52,3399.8 Q3.9@1556.52,3452.16 Q4.9@994.43,3416.32 Q4.9@1035.47,3427.94 Q4.9@1035.47,3473.21 Q4.9@1035.47,3518.49 Q4.9@1087.83,3427.94 Q4.9@1087.83,3473.21 Q4.9@1087.83,3478.53 Q4.9@1087.83,3518.49 Q4.9@1140.2,3427.94 Q4.9@1140.2,3473.21 Q4.9@1140.2,3518.49 Q4.9@1181.24,3416.32 Q5.9@1690.92,3416.32 Q5.9@1731.96,3427.94 Q5.9@1731.96,3473.21 Q5.9@1731.96,3518.49 Q5.9@1784.32,3427.94 Q5.9@1784.32,3473.21 Q5.9@1784.32,3478.53 Q5.9@1784.32,3518.49 Q5.9@1836.68,3427.94 Q5.9@1836.68,3473.21 Q5.9@1836.68,3518.49 Q5.9@1877.73,3416.32 U1.58 U2.58 U5.1 U8.1 U8.2 U8.3 U8.4 U8.9 U8.15 U8.16 U8.17 U8.18 U9.5 U9.15 U9.19 U9.20 U9.21 U9.22 U9.27 U9.28 U9.29 U9.30 U10.11 U10.13 U10.15 U10.16 U10.17 U10.19

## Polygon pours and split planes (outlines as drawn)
GND on SIG03 "TOP_LAYER_GND_POUR" (solid, remove dead copper, pour order 518): 7061.12,25.49 25.49,25.49 25.49,5092.62 7061.12,5092.62
BAT_IN on SIG03 "BAT_IN_L03_P515" (solid, pour order 515): 761.37,807.96 761.37,194.62 760.62,193.87 2278.87,193.87 2279,194 2279,946 2281,948 901.31,948 761.39,808.08
PVDD on SIG03 "PVDD_L03_P478" (solid, pour order 478): 3405,4293.53 3405,3980.59 3226,3801.59 3226,3656 3226,2638.27 6327.95,2638.27 6327.95,3370 5700.58,3370 4777.06,4293.53
V_boost on SIG03 "V_BOOST_L03_P467" (solid, pour order 467): 1017.34,4288.99 1017.34,4036.62 3373.62,4036.62 3374,4037 3374,4501 2180.16,4501 1968.15,4288.99
NetC158_1 on SIG03 "NETC158_1_L03_P466" (solid, pour order 466): 933.96,4033.9 1857.36,4033.9 1936.94,3954.32 1936.94,3481.73 753.3,3481.73 753.3,3858.1 815.17,3918.3
14_4V on SIG03 "14_4V_L03_P451" (solid, pour order 451): 494.7,1911.58 740.57,2157.46 740.57,2415.36 825.92,2500.71 881.16,2500.7 1000.76,2381.11 1211.87,2170 1382.02,2170 1462.02,2250 1462.02,2463.48 1508.81,2510.28 1571.17,2510.28 1696.27,2385.17 2105.98,1975.46 2105.98,1909.5
14_4V on SIG03 "Poly_14_4_03" (solid, remove dead copper, pour order 450): 918.19,1275.54 583.65,1275.54 494.69,1364.49 494.7,1911.58 567.76,1984.65 1294.35,1984.65 2289.5,1984.65 2375.84,1898.32 2375.84,1758.63 2315.56,1698.36 1063.36,1698.36 974.77,1609.77 974.77,1332.12
GND on SIG04 "TOP_LAYER_GND_POUR" (solid, remove dead copper, pour order 520): 7061.12,25.49 25.49,25.49 25.49,5092.62 7061.12,5092.62
BAT_IN on SIG04 "BAT_IN_L04_P516" (solid, pour order 516): 761.37,807.96 761.37,194.62 760.62,193.87 2278.87,193.87 2279,194 2279,946 2281,948 901.31,948 761.39,808.08
NetC77_1 on SIG04 "SIG03_NETC66_2_P364" (solid, pour order 495): 6491.22,2415.72 6723.32,2415.72 6723.32,2812.57 6349.76,3186.13 6014.71,3186.13 6014.71,3058.57 6187.65,3058.57 6491.22,2755.01
NetC26_1 on SIG04 "SIG03_NETC207_2_P365" (solid, remove dead copper, pour order 18): 2622.54,2423 2769.12,2423 2787.97,2441.85 2787.97,2459.87 3421.52,3093.42 3566.91,3093.42 3566.91,3192.07 3268.16,3192.07 2615.55,2539.46 2615.55,2429.98
NetC78_1 on SIG04 "NETC78_1_L04_P510" (solid, pour order 510): 6150.35,2986.62 6150.35,2806.28 6225.55,2731.08 6225.55,2416.38 6451.31,2416.38 6451.3,2779.25 6243.91,2986.65
NetC79_1 on SIG04 "NETC79_1_L04_P507" (solid, pour order 507): 5997.17,2805.55 6117.32,2805.55 6207.87,2715 6207.87,2416.81 6207.43,2416.38 5997.17,2416.38
NetC80_1 on SIG04 "NETC80_1_L04_P505" (solid, pour order 505): 5834.77,2979.76 5834.77,2651.63 5712.82,2529.68 5712.82,2416.99 5713.43,2416.38 5917.5,2416.38 5917.5,2473.87 5959.36,2515.73 5959.36,2910.35 5890.08,2979.63
NetC81_1 on SIG04 "NETC81_1_L04_P502" (solid, pour order 502): 5822.67,2979.63 5784.87,2979.63 5719.93,2914.68 5719.93,2754.16 5505.47,2539.7 5505.47,2416.76 5691.72,2416.76 5691.72,2525.12 5822.67,2656.06
NetC82_1 on SIG04 "NETC82_1_L04_P501" (solid, pour order 501): 5668.05,2785.86 5653.64,2800.26 5599.35,2800.26 5584.94,2785.86 5409.95,2785.86 5196.7,2572.61 5196.7,2416.92 5381.91,2416.92 5383.03,2418.04 5383.03,2500.84 5566.01,2683.82 5641.54,2683.82 5668.05,2710.33
NetC83_1 on SIG04 "NETC83_1_L04_P499" (solid, pour order 499): 5483.7,2988.37 5395.84,2988.37 4988.26,2580.79 4988.26,2416.76 5167.13,2416.76 5167.13,2559.45 5483.7,2876.03
NetC84_1 on SIG04 "SIG03_NETC207_2_P365" (solid, remove dead copper, pour order 496): 4689.89,2423 4836.47,2423 4855.33,2441.85 4855.33,2459.87 5488.23,3092.77 5637.1,3092.78 5637.1,3194.69 5338.14,3194.69 4682.91,2539.46 4682.91,2429.98
NetC20_1 on SIG04 "NETC20_1_L04_P493" (solid, pour order 493): 4082.99,2986.62 4082.99,2806.28 4158.2,2731.08 4158.2,2416.38 4383.95,2416.38 4383.95,2815.32 4212.6,2986.67
NetC21_1 on SIG04 "NETC21_1_L04_P490" (solid, pour order 490): 3929.81,2805.55 4049.96,2805.55 4140.51,2715 4140.51,2416.81 4140.08,2416.38 3929.81,2416.38
NetC22_1 on SIG04 "NETC22_1_L04_P488" (solid, pour order 488): 3767.42,2979.76 3767.42,2651.63 3645.46,2529.68 3645.46,2416.99 3646.08,2416.38 3850.14,2416.38 3850.14,2473.87 3892,2515.73 3892,2910.35 3822.73,2979.63
NetC23_1 on SIG04 "NETC23_1_L04_P485" (solid, pour order 485): 3755.31,2979.63 3717.52,2979.63 3652.57,2914.68 3652.57,2754.16 3438.11,2539.7 3438.11,2416.76 3624.37,2416.76 3624.37,2525.12 3755.31,2656.06
NetC24_1 on SIG04 "NETC24_1_L04_P483" (solid, pour order 483): 3600.69,2785.86 3586.29,2800.26 3531.99,2800.26 3517.59,2785.86 3342.59,2785.86 3129.34,2572.61 3129.34,2416.92 3314.55,2416.92 3315.67,2418.04 3315.67,2500.84 3498.66,2683.82 3574.18,2683.82 3600.69,2710.33
NetC25_1 on SIG04 "NETC25_1_L04_P481" (solid, pour order 481): 3416.34,2988.37 3328.48,2988.37 2920.9,2580.79 2920.9,2416.76 3099.77,2416.76 3099.77,2559.45 3416.35,2876.03
NetC158_1 on SIG04 "NETC158_1_L04_P465" (solid, pour order 465): 933.96,4033.9 1857.36,4033.9 1936.94,3954.32 1936.94,3481.73 753.3,3481.73 753.3,3858.1 815.17,3918.3
14_4V on SIG04 "14_4V_L04_P452" (solid, pour order 452): 494.7,1911.58 740.57,2157.46 740.57,2408.11 838.5,2506.03 876.81,2506.03 1000.76,2382.09 1212.85,2170 1382.02,2170 1462.02,2250 1462.02,2436.87 1531.17,2506.02 1575.9,2506.02 1696.27,2385.65 2105.98,1975.94 2105.98,1909.5
14_4V on SIG04 "Poly_14_4V_04" (solid, remove dead copper, pour order 434): 918.19,1275.54 583.65,1275.54 494.69,1364.49 494.7,1911.58 567.76,1984.65 1294.35,1984.65 2289.5,1984.65 2375.84,1898.32 2375.84,1758.63 2315.56,1698.36 1063.36,1698.36 974.77,1609.77 974.77,1332.12
NetC19_1 on SIG04 "SIG03_NETC66_2_P364" (solid, pour order 12): 4422.49,2415.89 4654.6,2415.9 4654.6,2806.75 4281.04,3180.31 3945.98,3180.31 3945.98,3052.75 4172.01,3052.75 4422.5,2802.27
NetC20_1 on Top Layer "NETC20_1_L01_P491" (solid, pour order 491): 4054.93,2935.29 4096.53,2935.29 4121.11,2910.72 4177.56,2910.72 4190.17,2923.33 4190.17,2971.34 4179,2982.51 4121.49,2982.51 4094.03,2955.06 4055.18,2955.06
GND on Top Layer "TOP_LAYER_GND_POUR" (solid, remove dead copper, pour order 517): 7061.12,25.49 25.49,25.49 25.49,5092.62 7061.12,5092.62
PVDD on Top Layer "PVDD_L01_P509" (solid, pour order 509): 6137.58,3155.92 6163.11,3155.92 6187.64,3131.39 6187.64,3119.68 6194.2,3113.12 6285.86,3113.12 6285.86,3183.97 6282.73,3187.1 6169.42,3187.1 6157.94,3175.62 6137.59,3175.62
NetC77_1 on Top Layer "NETC77_1_L01_P511" (solid, pour order 511): 6136.37,3144.01 6104.83,3144.01 6094.59,3154.25 6094.59,3169.63 6084.29,3179.92 6033.1,3179.92 6024.31,3171.13 6024.31,3122.82 6035.27,3111.86 6083.04,3111.86 6095.58,3124.41 6136.37,3124.41
NetC78_1 on Top Layer "NETC78_1_L01_P508" (solid, pour order 508): 6122.28,2935.29 6163.89,2935.29 6188.46,2910.72 6244.92,2910.72 6255.4,2921.2 6255.4,2973.47 6246.36,2982.51 6188.84,2982.51 6161.39,2955.06 6122.54,2955.06
NetC79_1 on Top Layer "NETC79_1_L01_P506" (solid, pour order 506): 6027.78,2856.81 6027.78,2818.83 6001.22,2792.27 6001.22,2723.78 6007.47,2717.53 6065.52,2717.53 6075.08,2727.09 6075.08,2790.4 6046.89,2818.59 6046.89,2856.57
NetC80_1 on Top Layer "NETC80_1_L01_P504" (solid, pour order 504): 5869.94,2845.06 5869.94,2878.44 5833.13,2915.25 5833.13,2971.51 5840.48,2978.86 5876.84,2978.86 5903.33,2952.37 5903.33,2898.62 5889.31,2884.61 5889.31,2844.98
NetC81_1 on Top Layer "NETC81_1_L01_P503" (solid, pour order 503): 5775.26,2847.38 5775.26,2879.76 5754.42,2900.59 5754.42,2952.2 5780.55,2978.33 5818,2978.33 5823.54,2972.78 5823.54,2910.58 5794.89,2881.93 5794.89,2847.46
NetC82_1 on Top Layer "NETC82_1_L01_P500" (solid, pour order 500): 5618.33,2856.81 5618.33,2818.83 5588.23,2788.73 5588.23,2727.33 5598.02,2717.53 5656.07,2717.53 5665.63,2727.09 5665.63,2790.4 5637.44,2818.59 5637.44,2856.57 5637.2,2856.81
NetC83_1 on Top Layer "NETC83_1_L01_P498" (solid, pour order 498): 5551.52,2954.89 5498.75,2954.89 5473.55,2980.09 5408.63,2980.09 5397.39,2968.85 5397.39,2919.35 5410.99,2905.75 5469.01,2905.75 5498.39,2935.13 5551.7,2935.13 5551.84,2935.27
NetC84_1 on Top Layer "NETC84_1_L01_P497" (solid, pour order 497): 5515.62,3144.01 5558.66,3144.01 5567.78,3153.13 5567.78,3176.78 5578.45,3187.45 5623.75,3187.45 5633.13,3178.07 5633.13,3131.64 5621.96,3120.47 5564.12,3120.47 5560.18,3124.41 5515.41,3124.41
PVDD on Top Layer "PVDD_L01_P492" (solid, pour order 492): 4070.22,3155.92 4095.76,3155.92 4120.29,3131.39 4120.29,3119.68 4126.84,3113.12 4280.04,3113.12 4283.46,3116.54 4283.46,3168.61 4256.01,3196.06 4111.02,3196.06 4090.59,3175.62 4070.23,3175.62
NetC19_1 on Top Layer "NETC19_1_L01_P494" (solid, pour order 494): 4069.02,3144.01 4037.47,3144.01 4027.23,3154.25 4027.23,3169.63 4016.93,3179.92 3965.75,3179.92 3956.95,3171.13 3956.95,3122.82 3967.91,3111.86 4015.68,3111.86 4028.23,3124.41 4069.01,3124.41
NetC21_1 on Top Layer "NETC21_1_L01_P489" (solid, pour order 489): 3960.42,2856.81 3960.42,2818.83 3933.87,2792.27 3933.87,2723.78 3940.11,2717.53 3998.17,2717.53 4007.72,2727.09 4007.72,2790.4 3979.53,2818.59 3979.53,2856.57
NetC22_1 on Top Layer "NETC22_1_L01_P487" (solid, pour order 487): 3802.58,2845.06 3802.58,2878.44 3765.77,2915.25 3765.77,2971.51 3773.12,2978.86 3809.48,2978.86 3835.97,2952.37 3835.97,2898.62 3821.96,2884.61 3821.96,2844.98
NetC23_1 on Top Layer "NETC23_1_L01_P486" (solid, pour order 486): 3707.9,2847.38 3707.9,2879.76 3687.06,2900.59 3687.06,2952.2 3713.19,2978.33 3750.64,2978.33 3756.19,2972.78 3756.19,2910.58 3727.53,2881.93 3727.53,2847.46
NetC24_1 on Top Layer "NETC24_1_L01_P482" (solid, pour order 482): 3550.97,2856.81 3550.97,2818.83 3520.87,2788.73 3520.87,2727.33 3530.67,2717.53 3588.72,2717.53 3598.27,2727.09 3598.27,2790.4 3570.08,2818.59 3570.08,2856.57 3569.84,2856.81
NetC25_1 on Top Layer "NETC25_1_L01_P480" (solid, pour order 480): 3484.16,2954.89 3431.4,2954.89 3406.19,2980.09 3341.28,2980.09 3330.04,2968.85 3330.04,2919.35 3343.63,2905.75 3401.66,2905.75 3431.03,2935.13 3484.34,2935.13 3484.49,2935.27
NetC26_1 on Top Layer "NETC26_1_L01_P479" (solid, pour order 479): 3448.26,3144.01 3491.31,3144.01 3500.43,3153.13 3500.43,3176.78 3511.1,3187.45 3556.4,3187.45 3565.78,3178.07 3565.78,3131.64 3554.61,3120.47 3496.76,3120.47 3492.82,3124.41 3448.06,3124.41
V_boost on Top Layer "V_BOOST_L01_P470" (solid, pour order 470): 2209.03,4403.42 3348.43,4403.42 3348.43,3955.47 2209.03,3955.47
PVDD on Top Layer "PVDD_L01_P477" (solid, pour order 477): 3405,4240 3405,3855 4575,3855 4575,4240
NetC174_2 on Top Layer "NETC174_2_L01_P476" (solid, pour order 476): 4593.93,4375 4743.97,4375 4743.97,4057.79 4593.93,4057.79
NetC172_2 on Top Layer "NETC172_2_L01_P475" (solid, pour order 475): 4156.2,4375 4306.24,4375 4306.24,4057.79 4156.2,4057.79
NetC173_2 on Top Layer "NETC173_2_L01_P471" (solid, pour order 471): 3717.76,4375 3867.8,4375 3867.8,4057.79 3717.76,4057.79
V_boost on Top Layer "V_BOOST_L01_P469" (solid, pour order 469): 2683.34,4403.42 2910.14,4403.42 2910.14,4193.6 2683.34,4193.6
V_boost on Top Layer "V_BOOST_L01_P468" (solid, pour order 468): 2245,4403.42 2471.8,4403.42 2471.8,4193.6 2245,4193.6
NetC158_1 on Top Layer "NETC158_1_L01_P461" (solid, pour order 461): 981.69,3481.48 981.69,3499.36 925.45,3555.6 811.01,3555.6 810.77,3670.27 858.33,3717.83 901.47,3674.68 1179.57,3674.68 1194.15,3660.11 1194.15,3481.48
NetL13_1 on Top Layer "NETL13_1_L01_P457" (solid, pour order 457): 1909.72,2316.69 1936.81,2343.78 1936.81,2565.12 1706.48,2565.12 1700,2571.59 1636.8,2571.59 1636.79,2546.16 1865.08,2317.87
V_boost on Top Layer "V_BOOST_L01_P464" (solid, pour order 464): 1033.15,4028.23 1086.18,4028.23 1102.95,4045 1522.7,4045 1522.7,4213.8 1012.83,4213.8 1012.83,4086.3 1032.98,4066.16
NetC158_1 on Top Layer "NETC158_1_L01_P463" (solid, pour order 463): 1429.01,3867.13 1275.93,3867.13 1228.59,3914.46 1076.84,3914.46 1062.68,3928.62 1050.54,3928.62 1039,3940.16 1039,3985.9 1039.24,3986.14 1059.47,3986.14 1101.95,4028.62 1518.95,4028.62 1518.96,4028.63 1518.96,3867.1 1519.03,3867.03
NetC158_1 on Top Layer "NETC158_1_L01_P462" (solid, pour order 462): 1678.17,3481.48 1678.17,3499.36 1621.94,3555.6 1501.61,3555.6 1501.38,3668.22 1549.31,3716.15 1589.54,3675.92 1867.93,3675.92 1890.63,3653.22 1890.63,3481.48
SW2 on Top Layer "SW2_L01_P460" (solid, pour order 460): 1444.65,3190.66 1444.65,3368.47 1501.49,3425.31 1601.65,3425.31 1668.51,3358.45 1819.89,3358.45 1819.89,3311.59 1937.19,3233.59 1937.19,3190.82
SW1 on Top Layer "SW1_L01_P459" (solid, pour order 459): 753.3,3190.15 753.3,3369.95 808.15,3424.8 908.3,3424.8 975.17,3357.94 1124.43,3357.94 1124.43,3312.49 1243.85,3233.08 1243.85,3190.31
14_4V on Top Layer "14_4V_L01_P453" (solid, pour order 453): 761.79,2185.21 761.79,2498.25 962.17,2498.25 1007.34,2453.08 1007.34,2328.45 1062.92,2272.88 1062.92,2184.83
NetL12_1 on Top Layer "NETL12_1_L01_P456" (solid, pour order 456): 1204.95,2316.79 1244.15,2356 1244.15,2565.12 1013.82,2565.12 1007.34,2571.59 944.14,2571.59 944.14,2546.76 1173.27,2317.63
14_4V on Top Layer "14_4V_L01_P454" (solid, pour order 454): 1454.5,2185.21 1454.5,2498.25 1654.05,2498.25 1700.05,2452.24 1700.05,2325.94 1755.62,2270.37 1755.62,2184.83
14_4V on Top Layer "Poly_14_4_01" (solid, remove dead copper, pour order 449): 918.19,1275.54 583.65,1275.54 494.69,1364.49 494.7,1911.58 567.76,1984.65 1294.35,1984.65 2289.5,1984.65 2375.84,1898.32 2375.84,1758.63 2315.56,1698.36 1063.36,1698.36 974.77,1609.77 974.77,1332.12
14_4V on Top Layer "Mechanical 1-No Net" (solid, remove dead copper, pour order 448): 740.57,1272.77 695.9,1317.44 613.92,1317.44 553.32,1317.44 540,1330.77 540,1453.35 548.61,1461.96 836.43,1461.96 853.39,1445 853.39,1295.69 830.47,1272.77
GND on Bottom Layer "TOP_LAYER_GND_POUR" (solid, remove dead copper, pour order 519): 7061.12,25.49 25.49,25.49 25.49,5092.62 7061.12,5092.62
